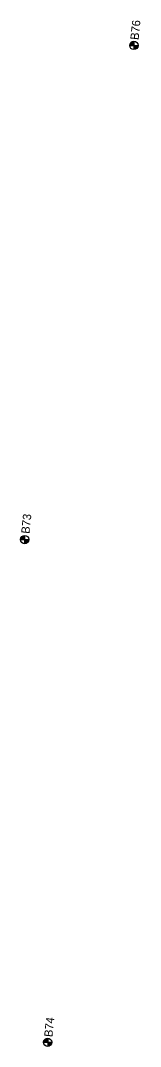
# Model space of a CAD drawing. Extents: x 345549 to 379569, y 127949 to 230467.
# Drawn here: x 359795 to 359939, y 170642 to 171874 of the extents above; entities that cross this region are included whole.
import ezdxf

# ---------------------------------------------------------------- set-up
doc = ezdxf.new("R2010")
doc.units = 0
for name, color, linetype in [('E_SOIL_BORE1 [KAPUR_CADDS_LEVELS]', 7, 'Continuous'), ('E_SOIL_BORE2 [KAPUR_CADDS_LEVELS]', 7, 'Continuous'), ('P_MARK', 7, 'Continuous')]:
    doc.layers.add(name, color=color, linetype=linetype)

msp = doc.modelspace()

# ---------------------------------------------------------------- linework, layer by layer
at = {"layer": 'P_MARK'}
for p, q in [((359926.5, 171844), (359936.5, 171844)), ((359931.5, 171849), (359931.5, 171839)), ((359800.3, 171255.9), (359800.3, 171245.9)), ((359795.3, 171250.9), (359805.3, 171250.9)), ((359828, 170652.5), (359828, 170642.5)), ((359823, 170647.5), (359833, 170647.5))]:
    msp.add_line(p, q, dxfattribs=at)
for centre in [(359931.5, 171844), (359800.3, 171250.9), (359828, 170647.5)]:
    msp.add_circle(centre, 5, dxfattribs=at)
for centre, radius, start, end in [((359931.5, 171844), 4.5, 89.9869, 179.9869), ((359931.5, 171844), 4, 89.9869, 179.9869), ((359931.5, 171844), 3.5, 89.9869, 179.9869), ((359931.5, 171844), 3, 89.9869, 179.9869), ((359931.5, 171844), 2.5, 89.9869, 179.9869), ((359931.5, 171844), 2, 89.9869, 179.9869), ((359931.5, 171844), 1.5, 89.9869, 179.9869), ((359931.5, 171844), 1, 89.9869, 179.9869), ((359931.5, 171844), 0.5, 89.9869, 179.9869), ((359931.5, 171844), 4.5, 269.9869, 359.9869), ((359931.5, 171844), 4, 269.9869, 359.9869), ((359931.5, 171844), 3.5, 269.9869, 359.9869), ((359931.5, 171844), 3, 269.9869, 359.9869), ((359931.5, 171844), 2.5, 269.9869, 359.9869), ((359931.5, 171844), 2, 269.9869, 359.9869), ((359931.5, 171844), 1.5, 269.9869, 359.9869), ((359931.5, 171844), 1, 269.9869, 359.9869), ((359931.5, 171844), 0.5, 269.9869, 359.9869), ((359800.3, 171250.9), 4.5, 89.9869, 179.9869), ((359800.3, 171250.9), 4, 89.9869, 179.9869), ((359800.3, 171250.9), 3.5, 89.9869, 179.9869), ((359800.3, 171250.9), 3, 89.9869, 179.9869), ((359800.3, 171250.9), 2.5, 89.9869, 179.9869), ((359800.3, 171250.9), 2, 89.9869, 179.9869), ((359800.3, 171250.9), 1.5, 89.9869, 179.9869), ((359800.3, 171250.9), 1, 89.9869, 179.9869), ((359800.3, 171250.9), 0.5, 89.9869, 179.9869), ((359800.3, 171250.9), 4.5, 269.9869, 359.9869), ((359800.3, 171250.9), 4, 269.9869, 359.9869), ((359800.3, 171250.9), 3.5, 269.9869, 359.9869), ((359800.3, 171250.9), 3, 269.9869, 359.9869), ((359800.3, 171250.9), 2.5, 269.9869, 359.9869), ((359800.3, 171250.9), 2, 269.9869, 359.9869), ((359800.3, 171250.9), 1.5, 269.9869, 359.9869), ((359800.3, 171250.9), 1, 269.9869, 359.9869), ((359800.3, 171250.9), 0.5, 269.9869, 359.9869), ((359828, 170647.5), 4.5, 89.9869, 179.9869), ((359828, 170647.5), 4, 89.9869, 179.9869), ((359828, 170647.5), 3.5, 89.9869, 179.9869), ((359828, 170647.5), 3, 89.9869, 179.9869), ((359828, 170647.5), 2.5, 89.9869, 179.9869), ((359828, 170647.5), 2, 89.9869, 179.9869), ((359828, 170647.5), 1.5, 89.9869, 179.9869), ((359828, 170647.5), 1, 89.9869, 179.9869), ((359828, 170647.5), 0.5, 89.9869, 179.9869), ((359828, 170647.5), 4.5, 269.9869, 359.9869), ((359828, 170647.5), 4, 269.9869, 359.9869), ((359828, 170647.5), 3.5, 269.9869, 359.9869), ((359828, 170647.5), 3, 269.9869, 359.9869), ((359828, 170647.5), 2.5, 269.9869, 359.9869), ((359828, 170647.5), 2, 269.9869, 359.9869), ((359828, 170647.5), 1.5, 269.9869, 359.9869), ((359828, 170647.5), 1, 269.9869, 359.9869), ((359828, 170647.5), 0.5, 269.9869, 359.9869)]:
    msp.add_arc(centre, radius, start, end, dxfattribs=at)

# ---------------------------------------------------------------- texts
at = {"layer": 'E_SOIL_BORE1 [KAPUR_CADDS_LEVELS]'}
for s, p in [('B73', (359806, 171257.5)), ('B74', (359833.6, 170653.4))]:
    msp.add_text(s, height=10, rotation=84.1728, dxfattribs=at).set_placement(p)
at = {"layer": 'E_SOIL_BORE2 [KAPUR_CADDS_LEVELS]'}
msp.add_text('B76', height=10, rotation=84.1728, dxfattribs=at).set_placement((359937.1, 171850.2))

doc.saveas('drawing.dxf')
